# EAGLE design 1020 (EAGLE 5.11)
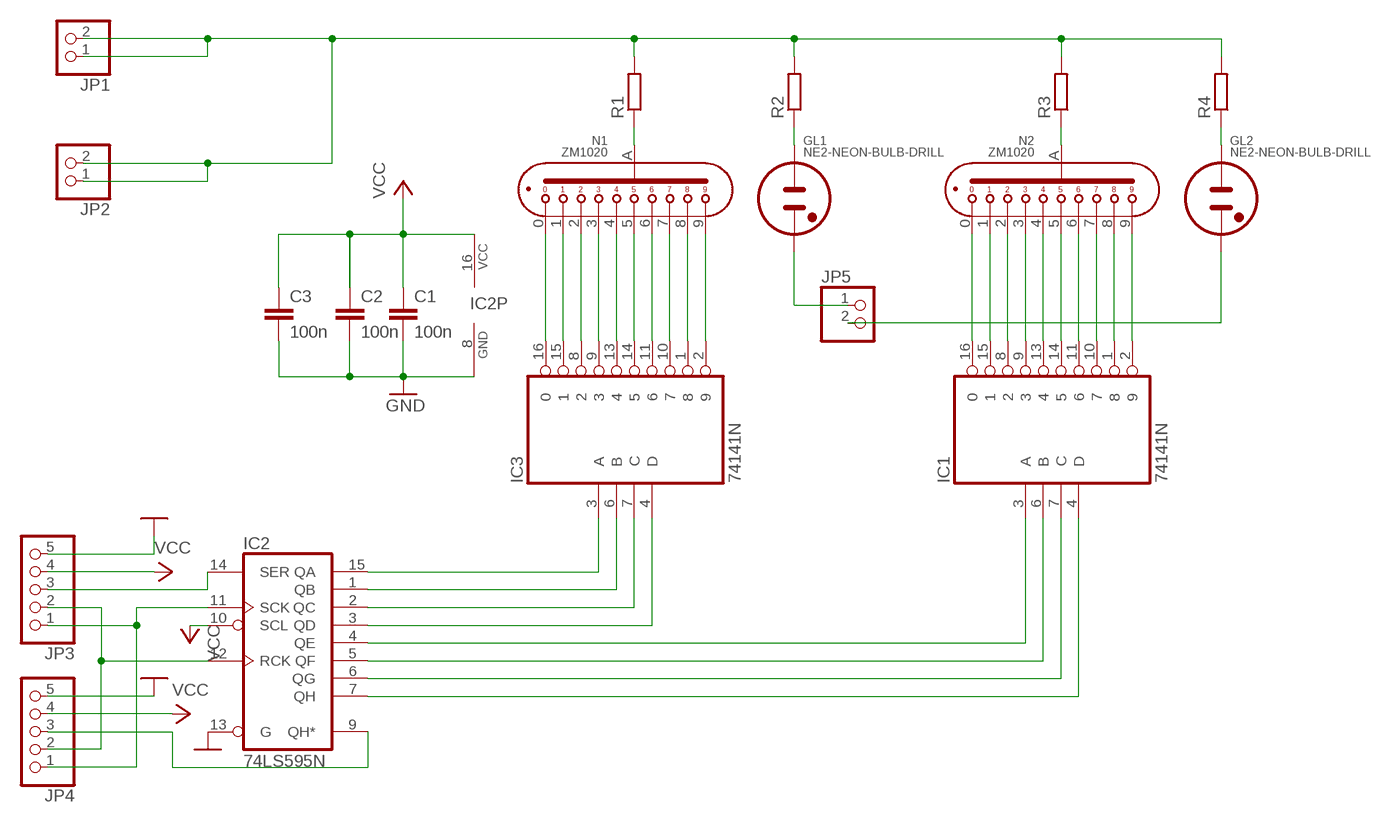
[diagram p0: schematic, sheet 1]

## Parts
C1  100n  C-EU025_050-025X075  [C025_050-025X075]
C2  100n  C-EU025_050-025X075  [C025_050-025X075]
C3  100n  C-EU025_050-025X075  [C025_050-025X075]
GL1  NE2-NEON-BULB-DRILL  [NE2-NEON-BULB-DRILL]
GL2  NE2-NEON-BULB-DRILL  [NE2-NEON-BULB-DRILL]
IC1  74141N  [DIL16]
IC2  74LS595N  [DIL16]
IC3  74141N  [DIL16]
JP1  PINHD-1X2  [1X02]
JP2  PINHD-1X2  [1X02]
JP3  PINHD-1X5  [1X05]
JP4  PINHD-1X5  [1X05]
JP5  PINHD-1X2  [1X02]
N1  ZM1020  [ZM1020]
N2  ZM1020  [ZM1020]
R1  R-EU_0207/12  [0207/12]
R2  R-EU_0207/12  [0207/12]
R3  R-EU_0207/12  [0207/12]
R4  R-EU_0207/12  [0207/12]

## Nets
GND: C1.2 C2.2 C3.2 IC2.8(GND) IC2.13(G) JP3.5 JP4.5
N$1: IC3.16 N1.0
N$2: IC3.15 N1.1
N$3: IC3.8 N1.2
N$4: IC3.9 N1.3
N$5: IC3.13 N1.4
N$6: IC3.14 N1.5
N$7: IC3.11 N1.6
N$8: IC3.10 N1.7
N$9: IC3.1 N1.8
N$10: IC3.2 N1.9
N$11: N1.A R1.1
N$12: GL1.1(A) R2.1
N$14: JP1.1 JP1.2 JP2.1 JP2.2 R1.2 R2.2 R3.2 R4.2
N$15: IC1.16 N2.0
N$16: IC1.15 N2.1
N$17: IC1.8 N2.2
N$18: IC1.9 N2.3
N$19: IC1.13 N2.4
N$20: IC1.14 N2.5
N$21: IC1.11 N2.6
N$22: IC1.10 N2.7
N$23: IC1.1 N2.8
N$24: IC1.2 N2.9
N$25: N2.A R3.1
N$26: GL2.1(A) R4.1
N$27: GL1.2(A1) JP5.1
N$28: IC2.15(QA) IC3.3(A)
N$29: IC2.1(QB) IC3.6(B)
N$30: IC2.2(QC) IC3.7(C)
N$31: IC2.3(QD) IC3.4(D)
N$32: IC1.3(A) IC2.4(QE)
N$33: IC1.6(B) IC2.5(QF)
N$34: IC1.7(C) IC2.6(QG)
N$35: IC1.4(D) IC2.7(QH)
N$37: GL2.2(A1) JP5.2
N$40: IC2.14(SER) JP3.3
N$41: IC2.11(SCK) JP3.1 JP4.1
N$42: IC2.12(RCK) JP3.2 JP4.2
N$45: IC2.9(QH*) JP4.3
VCC: C1.1 C2.1 C3.1 IC2.10(SCL) IC2.16(VCC) JP3.4 JP4.4

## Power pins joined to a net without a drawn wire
GND: IC1.12(GND) IC3.12(GND)
VCC: IC1.5(VCC) IC3.5(VCC)

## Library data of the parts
C1-C3 = resistor:C-EU: CAPACITOR, European symbol
GL1 GL2 = nixies:NE2-NEON-BULB: Neon indicator (wire connection)
IC1 IC3 = 74xx-eu:74*141: BCD to decimal DECODER/DRIVER
IC2 = 74xx-us:74*595: 8-bit SHIFT REGISTER, output latch
JP1 JP2 JP5 = pinhead:PINHD-1X2: PIN HEADER
JP3 JP4 = pinhead:PINHD-1X5: PIN HEADER
N1 N2 = zm1020:ZM1020: ZM1020: medium numeric topview nixie tube
R1-R4 = resistor:R-EU_: RESISTOR, European symbol

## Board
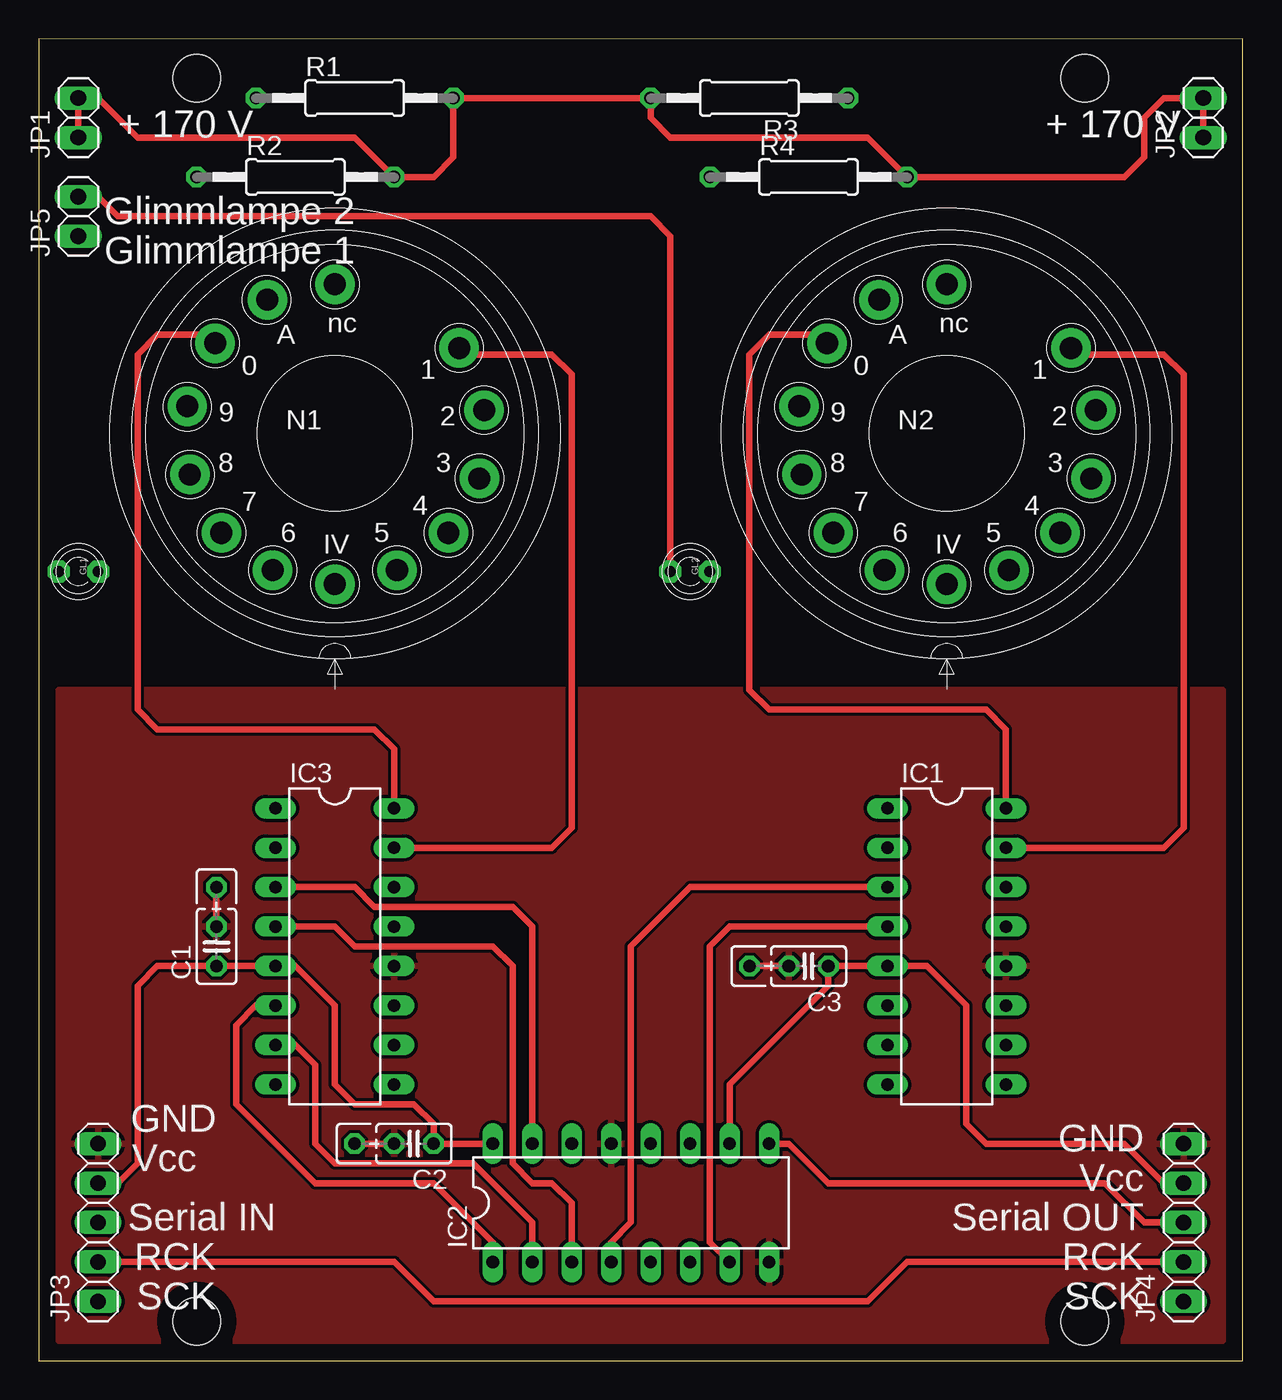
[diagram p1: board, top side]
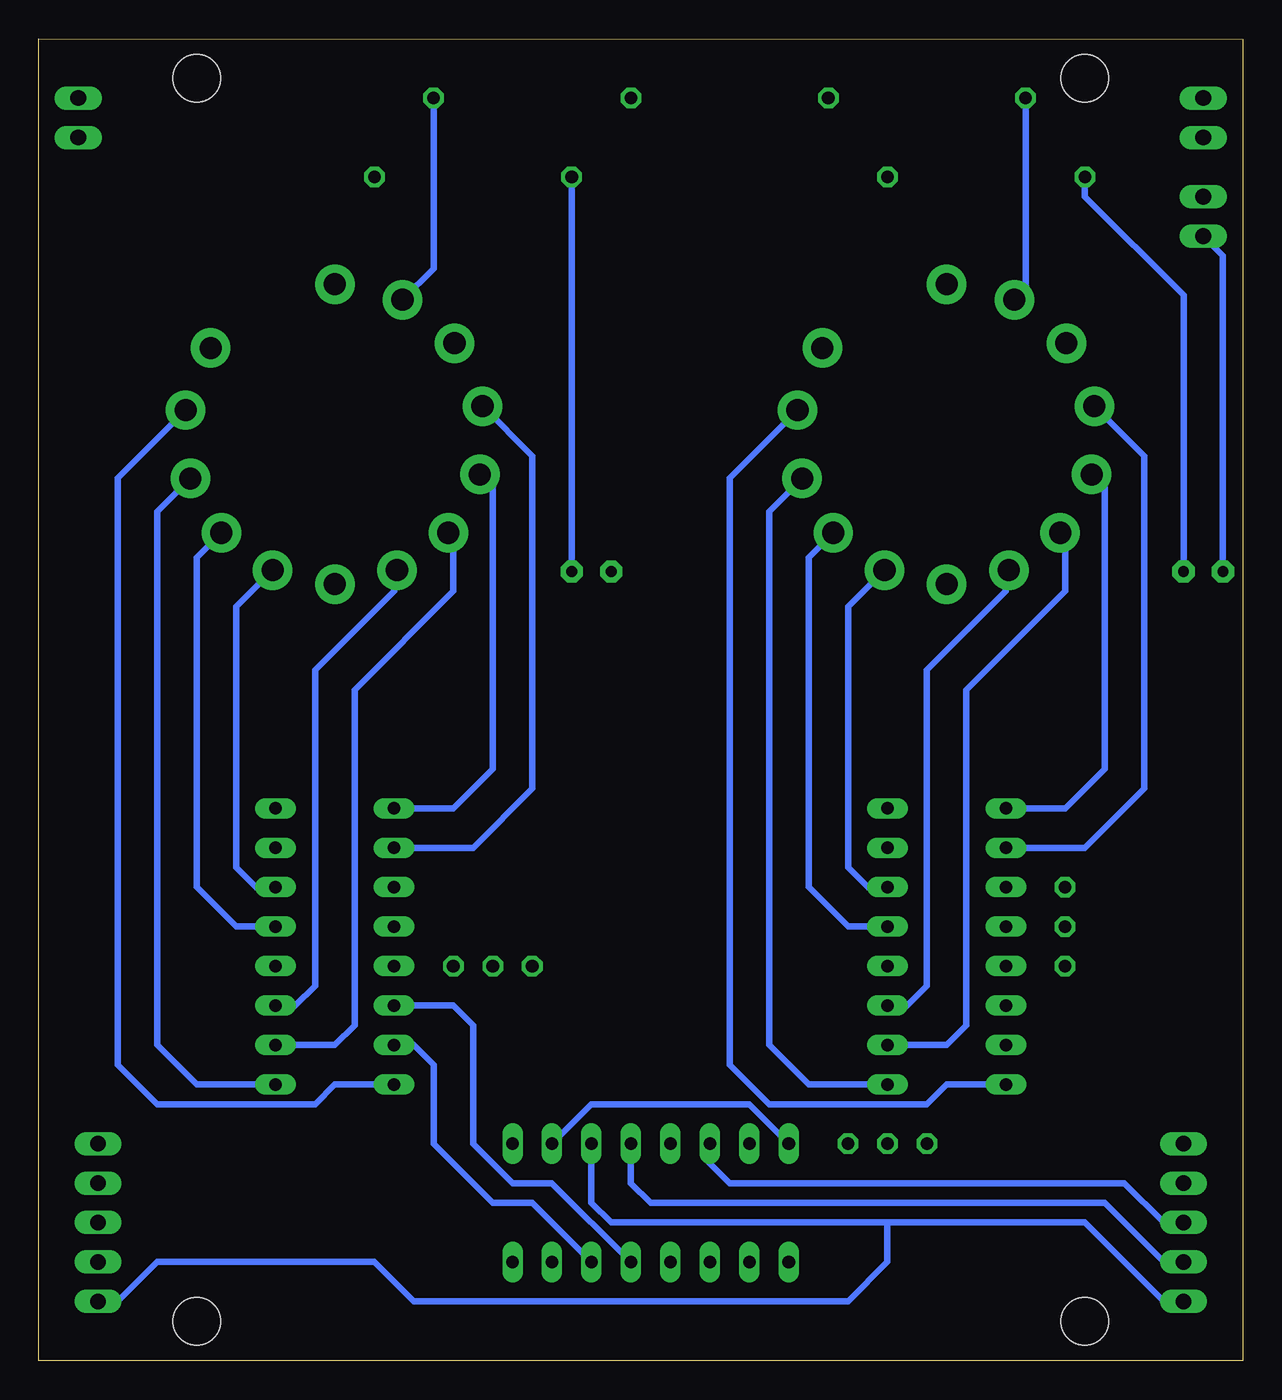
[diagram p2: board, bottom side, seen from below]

Size 77.47 x 85.09 mm. Coordinates in mm from the lower left corner, seen from the top.
Outline: 0,0 77.47,0 77.47,85.09 0,85.08 0,0
Copper layers (1*16): Top 0.035mm / dielectric 1.5mm / Bottom 0.035mm
Design rules "default": minimum track width 10mil, minimum drill 24mil, track to track 8mil, track to pad 8mil, pad to pad 8mil, via to via 8mil, smd to smd 8mil, copper to edge 40mil, drill to drill 8mil, minimum pad ring 10mil, minimum via ring 8mil, stop-mask expansion 4mil, vias tented up to drill 0mil, thermal gap 10mil
Holes 3.05 mm at 10.16,82.55 67.31,82.55 67.31,2.54 10.16,2.54

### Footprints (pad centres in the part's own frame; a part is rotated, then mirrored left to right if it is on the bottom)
C025_050-025X075 = drill 0.813 octagon: 1 -1.27,0; 2 1.27,0; 3 3.81,0
NE2-NEON-BULB-DRILL = drill 0.7 pad 1.422 octagon: 1 0,1.27; 2 0,-1.27
DIL16 = drill 0.813 long: 1 -8.89,-3.81; 2 -6.35,-3.81; 3 -3.81,-3.81; 4 -1.27,-3.81; 5 1.27,-3.81; 6 3.81,-3.81; 7 6.35,-3.81; 8 8.89,-3.81; 9 8.89,3.81; 10 6.35,3.81; 11 3.81,3.81; 12 1.27,3.81; 13 -1.27,3.81; 14 -3.81,3.81; 15 -6.35,3.81; 16 -8.89,3.81
1X02 = drill 1.016 long: 1 -1.27,0; 2 1.27,0
1X05 = drill 1.016 long: 1 -5.08,0; 2 -2.54,0; 3 0,0; 4 2.54,0; 5 5.08,0
ZM1020 = drill 1.422 pad 2.54 round: 0 -7.7,5.8; 1 8,5.5; 2 9.6,1.5; 3 9.3,-2.9; 4 7.3,-6.4; 5 4,-8.8; 6 -4,-8.8; 7 -7.3,-6.4; 8 -9.327,-2.646; 9 -9.5,1.75; A -4.35,8.6; IV 0,-9.7; NC 0,9.6
0207/12 = drill 0.813 octagon: 1 -6.35,0; 2 6.35,0

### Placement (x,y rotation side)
C1  11.43,26.67 90 top
C2  24.13,13.97 180 top
C3  49.53,25.4 180 top
GL1  2.54,50.8 270 top
GL2  41.91,50.8 270 top
IC1  58.42,26.67 270 top
IC2  38.1,10.16 0 top
IC3  19.05,26.67 270 top
JP1  2.54,80.01 90 top
JP2  74.93,80.01 90 top
JP3  3.81,8.89 90 top
JP4  73.66,8.89 90 top
JP5  2.54,73.66 90 top
N1  19.05,59.69 0 top
N2  58.42,59.69 0 top
R1  20.32,81.28 0 top
R2  16.51,76.2 0 top
R3  45.72,81.28 180 top
R4  49.53,76.2 0 top

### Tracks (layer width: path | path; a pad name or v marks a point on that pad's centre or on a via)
GND
  Top 0.406: 20.32,13.97 C2.2 | 45.72,25.4 C3.2 | C1.2 11.43,30.48
  pour Top: 1.27,43.18 76.2,43.18 76.2,1.27 1.27,1.27
N$1
  Top 0.406: IC3.16 22.86,39.37 21.59,40.64 7.62,40.64 6.35,41.91 6.35,64.77 7.62,66.04 10.8,66.04 N1.0
N$2
  Top 0.406: IC3.15 33.02,33.02 34.29,34.29 34.29,63.5 33.02,64.77 27.47,64.77 N1.1
N$3
  Bottom 0.406: IC3.8 19.05,17.78 20.32,16.51 30.48,16.51 33.02,19.05 33.02,56.82 N1.2
N$4
  Bottom 0.406: IC3.9 27.94,17.78 30.48,20.32 30.48,54.66 N1.3
N$5
  Bottom 0.406: IC3.13 25.4,27.94 27.94,30.48 27.94,51.7 N1.4
N$6
  Bottom 0.406: IC3.14 24.13,30.48 25.4,31.75 25.4,48.54 N1.5
N$7
  Bottom 0.406: IC3.11 21.59,22.86 20.32,24.13 20.32,44.45 15.24,49.53 15.24,50.7 N1.6
N$8
  Bottom 0.406: IC3.10 19.05,20.32 17.78,21.59 17.78,43.18 11.43,49.53 11.43,52.97 N1.7
N$9
  Bottom 0.406: IC3.1 11.43,35.56 8.89,38.1 8.89,56.21 N1.8
N$10
  Bottom 0.406: IC3.2 10.16,33.02 6.35,36.83 6.35,58.24 N1.9
N$11
  Bottom 0.406: R1.1 13.97,69.02 N1.A
N$12
  Bottom 0.406: R2.1 10.16,74.93 3.81,68.58 GL1.1
N$14
  Top 0.406: JP1.1 JP1.2 3.81,81.28 6.35,78.74 20.32,78.74 R2.2 25.4,76.2 26.67,77.47 R1.2 R3.2 39.37,80.01 40.64,78.74 53.34,78.74 R4.2 69.85,76.2 71.12,77.47 71.12,80.01 72.39,81.28 JP2.2 JP2.1
N$15
  Top 0.406: IC1.16 62.23,40.64 60.96,41.91 46.99,41.91 45.72,43.18 45.72,64.77 46.99,66.04 50.17,66.04 N2.0
N$16
  Top 0.406: IC1.15 72.39,33.02 73.66,34.29 73.66,63.5 72.39,64.77 66.84,64.77 N2.1
N$17
  Bottom 0.406: IC1.8 58.42,17.78 59.69,16.51 69.85,16.51 72.39,19.05 72.39,56.82 N2.2
N$18
  Bottom 0.406: IC1.9 67.31,17.78 69.85,20.32 69.85,54.66 N2.3
N$19
  Bottom 0.406: IC1.13 64.77,27.94 67.31,30.48 67.31,51.7 N2.4
N$20
  Bottom 0.406: IC1.14 63.5,30.48 64.77,31.75 64.77,48.54 N2.5
N$21
  Bottom 0.406: IC1.11 60.96,22.86 59.69,24.13 59.69,44.45 54.61,49.53 54.61,50.7 N2.6
N$22
  Bottom 0.406: IC1.10 58.42,20.32 57.15,21.59 57.15,43.18 50.8,49.53 50.8,52.97 N2.7
N$23
  Bottom 0.406: IC1.1 50.8,35.56 48.26,38.1 48.26,56.21 N2.8
N$24
  Bottom 0.406: IC1.2 49.53,33.02 45.72,36.83 45.72,58.24 N2.9
N$25
  Bottom 0.406: R3.1 52.07,70.29 N2.A
N$26
  Bottom 0.406: GL2.1 R4.1
N$27
  Bottom 0.406: GL1.2 1.27,71.12 JP5.1
N$28
  Top 0.406: IC2.15 31.75,27.94 30.48,29.21 21.59,29.21 20.32,30.48 IC3.3
N$29
  Top 0.406: IC2.1 29.21,7.62 25.4,11.43 17.78,11.43 12.7,16.51 12.7,21.59 13.97,22.86 IC3.6
N$30
  Top 0.406: IC2.2 31.75,8.89 27.94,12.7 19.05,12.7 17.78,13.97 17.78,19.05 16.51,20.32 IC3.7
N$31
  Top 0.406: IC3.4 19.05,27.94 20.32,26.67 29.21,26.67 30.48,25.4 30.48,12.7 31.75,11.43 33.02,11.43 34.29,10.16 IC2.3
N$32
  Top 0.406: IC2.4 36.83,7.62 38.1,8.89 38.1,26.67 41.91,30.48 IC1.3
N$33
  Bottom 0.406: IC2.5 44.45,11.43 46.99,11.43 49.53,13.97 49.53,21.59 50.8,22.86 IC1.6
N$34
  Bottom 0.406: IC2.6 45.72,10.16 48.26,10.16 52.07,13.97 52.07,19.05 53.34,20.32 IC1.7
N$35
  Top 0.406: IC1.4 44.45,27.94 43.18,26.67 43.18,7.62 IC2.7
N$37
  Top 0.406: JP5.2 3.81,74.93 5.08,73.66 39.37,73.66 40.64,72.39 GL2.2
N$40
  Bottom 0.406: JP3.3 5.08,8.89 7.62,11.43 33.02,11.43 34.29,12.7 IC2.14
N$41
  Bottom 0.406: JP3.1 5.08,3.81 10.16,8.89 22.86,8.89 | 22.86,8.89 40.64,8.89 41.91,10.16 IC2.11 | JP4.1 72.39,3.81 69.85,6.35 55.88,6.35 53.34,3.81 25.4,3.81 22.86,6.35 22.86,8.89
N$42
  Top 0.406: 72.39,6.35 JP4.2 55.88,6.35 53.34,3.81 25.4,3.81 22.86,6.35 JP3.2
  Bottom 0.406: JP3.2 5.08,6.35 8.89,10.16 38.1,10.16 39.37,11.43 IC2.12
N$45
  Top 0.406: IC2.9 48.26,13.97 50.8,11.43 68.58,11.43 71.12,8.89 JP4.3
VCC
  Top 0.406: JP3.4 5.08,11.43 6.35,12.7 6.35,24.13 7.62,25.4 C1.1 IC3.5 16.51,25.4 19.05,22.86 19.05,17.78 20.32,16.51 24.13,16.51 25.4,15.24 C2.1 IC2.16 | JP4.4 72.39,11.43 69.85,13.97 60.96,13.97 59.69,15.24 59.69,22.86 57.15,25.4 IC1.5 C3.1 50.8,24.13 44.45,17.78 IC2.10
  Bottom 0.406: IC2.16 31.75,16.51 41.91,16.51 IC2.10

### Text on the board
tPlace: + 170 V | + 170 V | Glimmlampe 2 | Glimmlampe 1 | GND | GND | Vcc | Vcc | Serial IN | Serial OUT | RCK | RCK | SCK | SCK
